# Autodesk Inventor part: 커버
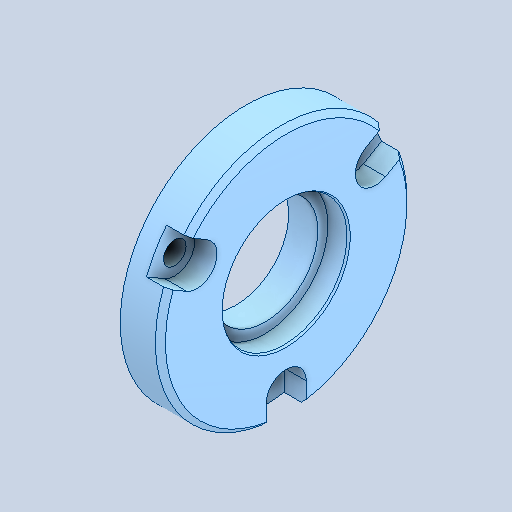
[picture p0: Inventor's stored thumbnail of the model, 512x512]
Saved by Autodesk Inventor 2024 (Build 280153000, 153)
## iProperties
Created: 2025-10
Part Number: 커버
Material: 알루미늄 6061
Document SubType Name: Modeling
Designer: EDU03
Density: 2.7 g/cm^3
Appearance: 기본값
Author: jhkim
Sending System: Autodesk Inventor 2026
Preprocessor: ST-DEVELOPER v20.1
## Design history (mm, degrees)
feature "솔리드1"
node "솔리드2"
